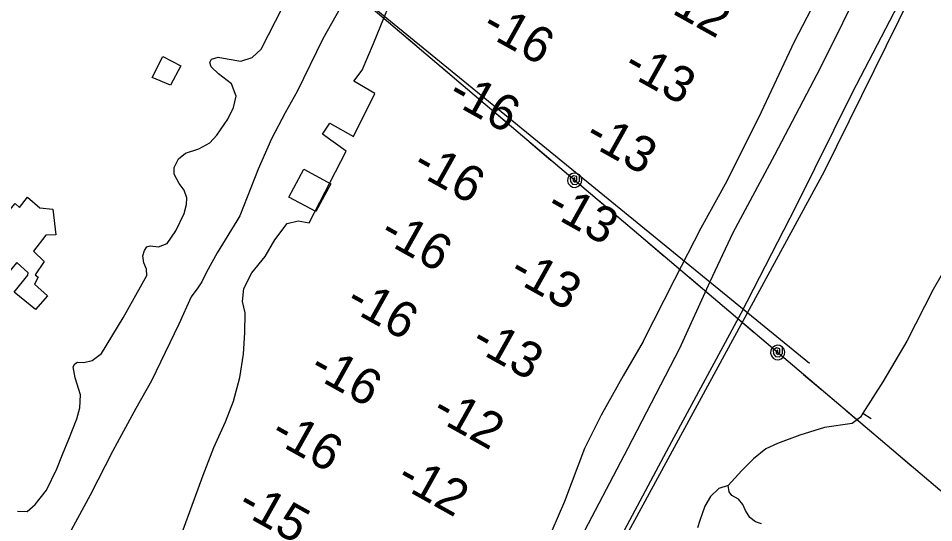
# Model space of a CAD drawing. Extents: x 3683402 to 3721514, y 487807 to 513565.
# Drawn here: x 3700378 to 3701526, y 501651 to 502284 of the extents above; entities that cross this region are included whole.
import ezdxf

# ---------------------------------------------------------------- set-up
doc = ezdxf.new("R2010")
doc.units = 0
for name, color, linetype in [('V-BLDG-OTLN', 7, 'Continuous'), ('V-LEVE-TOET', 7, 'Continuous'), ('V-SITE-OTLN', 7, 'Continuous'), ('V-TOPO-SHOR', 7, 'Continuous'), ('V-TOPO-SPOT', 7, 'Continuous'), ('V-UTIL-LINE', 7, 'Continuous')]:
    doc.layers.add(name, color=color, linetype=linetype)

msp = doc.modelspace()

# ---------------------------------------------------------------- linework, layer by layer
at = {"layer": 'V-BLDG-OTLN'}
for points in [[(3700559.3, 502236.5), (3700582, 502224.8), (3700568.9, 502200.5), (3700546.2, 502210.2)], [(3700717.5, 502060), (3700736.3, 502094.8), (3700770.2, 502076.5), (3700751.4, 502041.7)], [(3700336.2, 501995.7), (3700355.5, 502017.3), (3700349.6, 502022.9), (3700374.1, 502052.1), (3700379.7, 502047.1), (3700389.7, 502059.7), (3700405.2, 502046.3), (3700421.4, 502045), (3700425.1, 502012.5), (3700412.8, 502012.2), (3700397.2, 501992), (3700410.7, 501979.2), (3700399.3, 501962.6), (3700403.2, 501959.6), (3700398.5, 501950.6), (3700414.8, 501936.1), (3700399.7, 501919), (3700373.1, 501940.7), (3700390.1, 501962), (3700390.6, 501965.1), (3700376.3, 501978), (3700367.4, 501967.3)]]:
    msp.add_lwpolyline(points, close=True, dxfattribs=at)
at = {"layer": 'V-LEVE-TOET'}
for points in [[(3701502, 502341.1), (3701423.6, 502190.8), (3701352.9, 502048.3), (3701284.2, 501914.1), (3701197.1, 501753), (3701138, 501641.7)], [(3701075.1, 501616.3), (3701142.4, 501744.7), (3701207.7, 501870.6), (3701245.9, 501954), (3701274.5, 502015.5), (3701326.7, 502113.1), (3701384.3, 502222.9), (3701440, 502335.6)], [(3700787, 502306.5), (3700760.2, 502258.3), (3700728, 502192.4), (3700712.9, 502165.8), (3700695.8, 502132.9), (3700678.8, 502095.1), (3700655.9, 502036.6), (3700652, 502030.2), (3700627.6, 501989.9), (3700614, 501965.8), (3700608.1, 501953.5), (3700603.2, 501946.1), (3700594.9, 501934.8), (3700579.3, 501900.4), (3700545.2, 501829.6), (3700525.7, 501794.7), (3700507.7, 501761.7), (3700496.9, 501741.6)], [(3700377, 501666.1), (3700389.2, 501665.6), (3700399.5, 501674.5), (3700413.7, 501692.2), (3700426.4, 501719.2), (3700433.7, 501736.9), (3700441.4, 501756.1), (3700451.7, 501781.6), (3700455.5, 501795.4), (3700456, 501812.1), (3700449.5, 501833.2), (3700447, 501846.9), (3700449, 501850.8), (3700452.4, 501852.8), (3700460.2, 501852.3), (3700471, 501854.8), (3700482.3, 501863.7), (3700509.6, 501908.5), (3700539.4, 501961.6), (3700538.9, 501969.4), (3700535.4, 501977.3), (3700534.4, 501986.1), (3700536.3, 501993), (3700539.2, 501997.4), (3700543.7, 501998.9), (3700554, 501997.4), (3700564.8, 502001.9), (3700575.5, 502017.6), (3700586.2, 502039.3), (3700589.1, 502050.6), (3700589.6, 502058.9), (3700586.1, 502068.7), (3700579.7, 502077), (3700573.8, 502088.8), (3700573.8, 502097.1), (3700579.1, 502108), (3700587.9, 502114.9), (3700604.6, 502120.3), (3700618.3, 502128.2), (3700627.1, 502137.6), (3700640.8, 502157.7), (3700648.1, 502172.5), (3700651.5, 502186.7), (3700645.5, 502201.9), (3700629.3, 502214.6), (3700619.9, 502223.4), (3700618.4, 502228.8), (3700620.4, 502232.8), (3700628.7, 502235.7), (3700640, 502233.3), (3700657.2, 502230.4), (3700671.4, 502234.9), (3700682.7, 502245.7), (3700710, 502298.8)], [(3700496.9, 501741.6), (3700468.2, 501686), (3700444.3, 501642.2), (3700432.1, 501619.1), (3700431.1, 501610.8), (3700439, 501595.6), (3700451.9, 501581.4), (3700472, 501566.8), (3700487.8, 501557), (3700497.6, 501546.7), (3700499.1, 501541.3), (3700497.7, 501536.4), (3700490.3, 501528.5), (3700482, 501525.1), (3700463.3, 501532.9), (3700444.6, 501547.5), (3700429.8, 501562.2), (3700423.4, 501567.6), (3700413.2, 501561.7), (3700408.8, 501547.4), (3700402.5, 501520.9), (3700405.2, 501508.5)]]:
    msp.add_lwpolyline(points, dxfattribs=at)
at = {"layer": 'V-SITE-OTLN'}
msp.add_lwpolyline([(3701546.6, 501292.4), (3701471.9, 501317.9), (3701457.6, 501306.4), (3701426.2, 501246), (3701414.8, 501240.2), (3701386.1, 501243), (3701196, 501414.6), (3701132.7, 501477.5), (3701115.3, 501514.7), (3701115.2, 501557.8), (3701140.7, 501635.4), (3701388.9, 502092.6), (3701498.3, 502314)], dxfattribs=at)
at = {"layer": 'V-TOPO-SHOR'}
msp.add_line((3701437.3, 501788.8), (3701447.4, 501782.3), dxfattribs=at)
for points in [[(3701830.9, 502461.4), (3701791.3, 502384.5), (3701730.7, 502285.1), (3701662.5, 502159.7), (3701609.5, 502077.9), (3701567.1, 502016.8), (3701525.5, 501943.9), (3701492.4, 501879.2), (3701462.1, 501828.3), (3701437.3, 501788.8), (3701434.2, 501783.9), (3701423.6, 501776.1), (3701389.1, 501771.1), (3701358.3, 501761.3), (3701330.3, 501751), (3701315.3, 501744.1), (3701299.9, 501731.8), (3701285.3, 501717.1), (3701268.4, 501698.2)], [(3701161.7, 501878.9), (3701201.5, 501956.8), (3701234.3, 502021.4), (3701264.8, 502076.5), (3701306.9, 502159.9), (3701351.4, 502255.1), (3701420, 502387.3)], [(3700578.5, 501625.5), (3700594.4, 501668.8), (3700610, 501711.2), (3700623.2, 501745.8), (3700638.1, 501778.1), (3700647.8, 501804.1), (3700655.9, 501833.6), (3700660.5, 501863), (3700662.4, 501890.2), (3700662.7, 501914.9), (3700659.5, 501929), (3700661, 501945.1), (3700671.2, 501964.8), (3700687.6, 501985.3), (3700699.7, 502006.2), (3700715.4, 502027), (3700729.1, 502030.2), (3700742.9, 502027.5), (3700789.3, 502117.6), (3700759.4, 502139.1), (3700768.8, 502152.9), (3700798.3, 502136.1), (3700825.2, 502190), (3700798.8, 502205.3), (3700809.4, 502219.1), (3700823.4, 502252.5), (3700841.3, 502295.8)], [(3701161.7, 501878.9), (3701136.4, 501835.6), (3701109, 501786.4), (3701088, 501744.7), (3701063, 501678.2), (3701031.1, 501604.3)], [(3701268.4, 501698.2), (3701256.6, 501694.5), (3701246.1, 501684.3), (3701239.2, 501672.1), (3701235.6, 501662.7), (3701232.8, 501654.2), (3701230, 501645.2)], [(3701310, 501650), (3701302.7, 501652.4), (3701295.4, 501658.1), (3701290.1, 501667), (3701286.8, 501674.3), (3701281.1, 501681.2), (3701272.9, 501685.6), (3701269.7, 501690.1), (3701269.2, 501693.3), (3701268.4, 501698.2)]]:
    msp.add_lwpolyline(points, dxfattribs=at)
at = {"layer": 'V-UTIL-LINE'}
msp.add_line((3700657.9, 502433.5), (3701370.4, 501851.5), dxfattribs=at)
for points in [[(3706129.3, 497801), (3705828.8, 498068.5), (3705518.6, 498319.6), (3705215.1, 498577.2), (3704915.9, 498836.9), (3704693.9, 499026.2), (3704157.4, 499474.5), (3703735.3, 499831.2), (3703393.2, 500117.5), (3703044.2, 500410.8), (3702715.6, 500698.6), (3702052.3, 501252), (3701362.7, 501837.6), (3700635.7, 502454.8), (3700242, 502777.1), (3699904.9, 503059.6), (3699655.4, 503213.4), (3699371.4, 503385.3)], [(3700850.9, 502272.1), (3700876.9, 502250.1)], [(3700907.4, 502224.2), (3700933.3, 502202.2)], [(3700963.8, 502176.3), (3700989.7, 502154.3)], [(3701020.2, 502128.4), (3701046.1, 502106.4)], [(3701075.8, 502081.2), (3701076.1, 502084), (3701074.1, 502082.9), (3701073.9, 502080.2), (3701076.3, 502078.5), (3701078.6, 502081), (3701078.4, 502085.7), (3701074.3, 502086.8), (3701070.2, 502084.1), (3701070.4, 502079.5), (3701073.1, 502076), (3701077.9, 502075.9), (3701081.7, 502079.9), (3701081.7, 502088), (3701078.6, 502089.7), (3701075.1, 502090.1), (3701071.7, 502089.2), (3701069, 502087), (3701067.3, 502083.9), (3701066.9, 502080.4), (3701067.8, 502077.1), (3701070, 502074.3), (3701073.1, 502072.6), (3701076.6, 502072.2), (3701079.9, 502073.2), (3701082.7, 502075.4), (3701084.4, 502078.4), (3701084.8, 502081.9), (3701083.8, 502085.3), (3701081.7, 502088)], [(3701105.6, 502055.9), (3701131.5, 502033.9)], [(3701162, 502008), (3701187.9, 501986)], [(3701218.4, 501960.2), (3701244.3, 501938.1)], [(3701274.8, 501912.3), (3701300.7, 501890.3)], [(3701330.4, 501865), (3701330.7, 501867.9), (3701328.7, 501866.7), (3701328.5, 501864), (3701330.9, 501862.4), (3701333.2, 501864.8), (3701333, 501869.5), (3701328.9, 501870.7), (3701324.8, 501867.9), (3701325, 501863.4), (3701327.7, 501859.8), (3701332.5, 501859.7), (3701336.3, 501863.7), (3701336.3, 501871.9), (3701333.2, 501873.6), (3701329.7, 501874), (3701326.3, 501873), (3701323.6, 501870.8), (3701321.9, 501867.8), (3701321.5, 501864.3), (3701322.4, 501860.9), (3701324.6, 501858.1), (3701327.7, 501856.4), (3701331.2, 501856), (3701334.6, 501857), (3701337.3, 501859.2), (3701339, 501862.3), (3701339.4, 501865.7), (3701338.4, 501869.1), (3701336.3, 501871.9)], [(3701360.2, 501839.8), (3701362.7, 501837.6), (3701386.1, 501817.8)], [(3701416.6, 501791.9), (3701442.5, 501769.9)], [(3701473, 501744), (3701498.9, 501722)]]:
    msp.add_lwpolyline(points, dxfattribs=at)

# ---------------------------------------------------------------- texts
at = {"layer": 'V-TOPO-SPOT'}
for s, p in [('-12', (3701179, 502300.9)), ('-16', (3700957, 502267)), ('-13', (3701134.5, 502217.2)), ('-16', (3700914.3, 502181.7)), ('-13', (3701086, 502129.5)), ('-16', (3700870, 502092.8)), ('-13', (3701037.6, 502041.2)), ('-16', (3700828.9, 502007.5)), ('-13', (3700991.3, 501959.1)), ('-16', (3700786.4, 501922)), ('-13', (3700943.5, 501871.6)), ('-16', (3700740.9, 501838.2)), ('-12', (3700894.5, 501784.4)), ('-16', (3700692, 501756.3)), ('-12', (3700850.1, 501700.2)), ('-15', (3700650.5, 501666.7))]:
    msp.add_text(s, height=45, rotation=330.7933, dxfattribs=at).set_placement(p)

doc.saveas('drawing.dxf')
